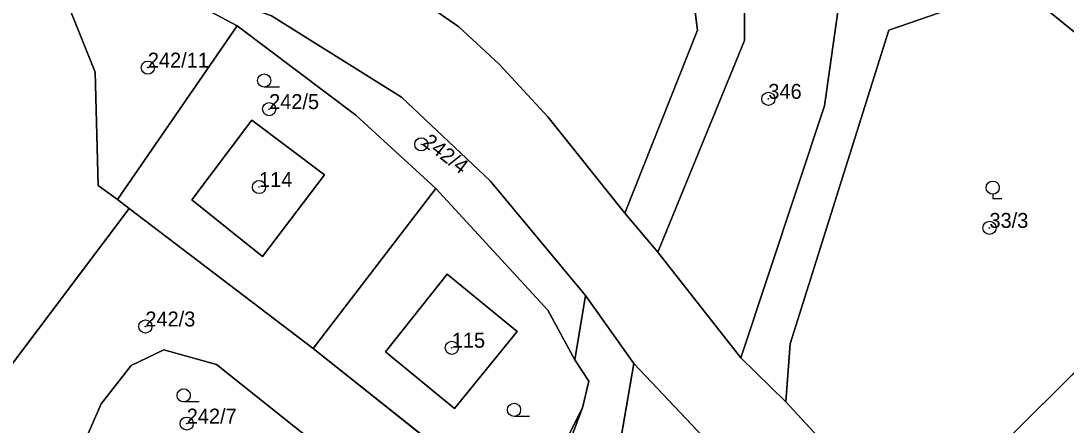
# Model space of a CAD drawing. Extents: x -652854 to -650068, y -1097661 to -1095417.
# Drawn here: x -650938.6 to -650819.6, y -1096045.2 to -1095999.2 of the extents above; entities that cross this region are included whole.
import ezdxf

# ---------------------------------------------------------------- set-up
doc = ezdxf.new("R2010")
doc.units = 0
for name, color, linetype in [('Definiční body parcel', 7, 'Continuous'), ('Hranice parcel', 7, 'Continuous'), ('Obvody jako plochy', 7, 'Continuous'), ('Parcelní čísla', 7, 'Continuous'), ('Značky kultur', 7, 'Continuous')]:
    doc.layers.add(name, color=color, linetype=linetype)

msp = doc.modelspace()

# ---------------------------------------------------------------- linework, layer by layer
at = {"layer": 'Definiční body parcel'}
for centre, radius in [((-650924.13, -1096004.54), 0.75), ((-650924.13, -1096004.54), 0.0327), ((-650853.49, -1096008.09), 0.75), ((-650853.49, -1096008.09), 0.0327), ((-650910.32, -1096009.26), 0.75), ((-650910.32, -1096009.26), 0.0327), ((-650893, -1096013.27), 0.75), ((-650893, -1096013.27), 0.0327), ((-650911.47, -1096018.13), 0.75), ((-650911.47, -1096018.13), 0.0327), ((-650828.32, -1096022.78), 0.75), ((-650828.32, -1096022.78), 0.0327), ((-650924.41, -1096034), 0.75), ((-650924.41, -1096034), 0.0327), ((-650889.53, -1096036.42), 0.75), ((-650889.53, -1096036.42), 0.0327), ((-650919.7, -1096045.05), 0.75), ((-650919.7, -1096045.05), 0.0327)]:
    msp.add_circle(centre, radius, dxfattribs=at)
at = {"layer": 'Hranice parcel'}
for p, q in [((-650861.57, -1096000.28), (-650865.79, -1095966.45)), ((-650856.25, -1095986.12), (-650856.19, -1096001.44)), ((-650888.72, -1095999.9), (-650906.97, -1095987.24)), ((-650913.95, -1095999.79), (-650928.95, -1095991.79)), ((-650847.08, -1096008.9), (-650844.73, -1095992.23)), ((-650934.27, -1095994.75), (-650930.14, -1096005.05)), ((-650839.79, -1096000.27), (-650825.13, -1095995.2)), ((-650825.13, -1095995.2), (-650797.14, -1096017.98)), ((-650895.24, -1096007.92), (-650910.04, -1095998.66)), ((-650927.6, -1096019.54), (-650913.95, -1095999.79)), ((-650913.95, -1095999.79), (-650900.46, -1096009.94)), ((-650884.15, -1096004.16), (-650888.72, -1095999.9)), ((-650869.83, -1096021.1), (-650861.57, -1096000.28)), ((-650851, -1096035.98), (-650839.79, -1096000.27)), ((-650856.19, -1096001.44), (-650866.08, -1096025.56)), ((-650878.58, -1096010.13), (-650884.15, -1096004.16)), ((-650930.14, -1096005.05), (-650929.8, -1096017.97)), ((-650885.14, -1096017.44), (-650895.24, -1096007.92)), ((-650856.61, -1096037.55), (-650847.08, -1096008.9)), ((-650919.13, -1096019.58), (-650912.29, -1096010.52)), ((-650912.29, -1096010.52), (-650904.02, -1096016.76)), ((-650900.46, -1096009.94), (-650891.33, -1096018.28)), ((-650869.83, -1096021.1), (-650878.58, -1096010.13)), ((-650904.02, -1096016.76), (-650911.07, -1096026.02)), ((-650874.29, -1096030.48), (-650885.14, -1096017.44)), ((-650929.8, -1096017.97), (-650927.6, -1096019.54)), ((-650891.33, -1096018.28), (-650905.32, -1096036.52)), ((-650878.59, -1096032.13), (-650891.33, -1096018.28)), ((-650797.14, -1096017.98), (-650837.43, -1096057.82)), ((-650927.6, -1096019.54), (-650926.24, -1096020.58)), ((-650911.07, -1096026.02), (-650919.13, -1096019.58)), ((-650926.24, -1096020.58), (-650947.07, -1096048.17)), ((-650926.24, -1096020.58), (-650905.32, -1096036.52)), ((-650866.08, -1096025.56), (-650869.83, -1096021.1)), ((-650866.08, -1096025.56), (-650856.61, -1096037.55)), ((-650890.06, -1096028.04), (-650897.06, -1096036.9)), ((-650882.07, -1096034.56), (-650890.06, -1096028.04)), ((-650874.29, -1096030.48), (-650875.52, -1096037.79)), ((-650868.81, -1096038.2), (-650874.29, -1096030.48)), ((-650875.52, -1096037.79), (-650878.59, -1096032.13)), ((-650889.23, -1096043.33), (-650882.07, -1096034.56)), ((-650922.29, -1096036.66), (-650926.04, -1096038.44)), ((-650916.32, -1096038.32), (-650922.29, -1096036.66)), ((-650905.32, -1096036.52), (-650886.47, -1096051.45)), ((-650851.49, -1096042.56), (-650851, -1096035.98)), ((-650897.06, -1096036.9), (-650889.23, -1096043.33)), ((-650873.91, -1096040.24), (-650875.52, -1096037.79)), ((-650856.61, -1096037.55), (-650851.49, -1096042.56)), ((-650926.04, -1096038.44), (-650929.43, -1096042.79)), ((-650904.71, -1096047.58), (-650916.32, -1096038.32)), ((-650868.81, -1096038.2), (-650871.08, -1096051.36)), ((-650844.12, -1096064.27), (-650868.81, -1096038.2)), ((-650874.66, -1096043.25), (-650873.91, -1096040.24)), ((-650929.43, -1096042.79), (-650935.88, -1096057.57)), ((-650837.43, -1096057.82), (-650851.49, -1096042.56)), ((-650874.66, -1096043.25), (-650884.57, -1096069.52)), ((-650875.54, -1096045.04), (-650874.66, -1096043.25)), ((-650878.99, -1096052.02), (-650875.54, -1096045.04))]:
    msp.add_line(p, q, dxfattribs=at)
at = {"layer": 'Obvody jako plochy'}
for points in [[(-650815.91, -1096079.94), (-650837.43, -1096057.82), (-650851.49, -1096042.56), (-650856.61, -1096037.55), (-650866.08, -1096025.56), (-650869.83, -1096021.1), (-650878.58, -1096010.13), (-650884.15, -1096004.16), (-650888.72, -1095999.9), (-650906.97, -1095987.24), (-650919.07, -1095983.1), (-650939.79, -1095976.94), (-650942.73, -1095975.31), (-650965.11, -1095955.28), (-650999.89, -1095931.88), (-651069.69, -1095883.2), (-651088.16, -1095874.33), (-651093.24, -1095871.75), (-651106.05, -1095871.75), (-651124.53, -1095872.94)], [(-651111.53, -1095882.37), (-651098.01, -1095884.51), (-651076.72, -1095891.08), (-651069.09, -1095896.55), (-651006, -1095940.92), (-650970.52, -1095965.45), (-650947.06, -1095985.27), (-650941.58, -1095987.24), (-650928.95, -1095991.79), (-650910.04, -1095998.66), (-650895.24, -1096007.92), (-650885.14, -1096017.44), (-650874.29, -1096030.48), (-650868.81, -1096038.2), (-650844.12, -1096064.27), (-650836.01, -1096073.17), (-650788.5, -1096124.42)], [(-650904.08, -1096145.3), (-650901.13, -1096135.45), (-650897.38, -1096119.26), (-650893.01, -1096103.89), (-650871.08, -1096051.36), (-650868.81, -1096038.2), (-650874.29, -1096030.48), (-650875.52, -1096037.79), (-650873.91, -1096040.24), (-650874.66, -1096043.25), (-650884.57, -1096069.52), (-650902.03, -1096119.57), (-650909.81, -1096151.69)]]:
    msp.add_lwpolyline(points, dxfattribs=at)
for points in [[(-650861.2, -1095966.88), (-650864, -1095957.32), (-650870.42, -1095945.56), (-650883.1, -1095928.38), (-650889.88, -1095920.1), (-650889.39, -1095918.87), (-650896.67, -1095915.35), (-650898.83, -1095918.21), (-650888.97, -1095929.69), (-650880.92, -1095939.45), (-650877.8, -1095945.22), (-650865.79, -1095966.45), (-650861.57, -1096000.28), (-650869.83, -1096021.1), (-650866.08, -1096025.56), (-650856.19, -1096001.44), (-650856.25, -1095986.12)], [(-650869.83, -1096021.1), (-650861.57, -1096000.28), (-650865.79, -1095966.45), (-650877.8, -1095945.22), (-650906.97, -1095987.24), (-650888.72, -1095999.9), (-650884.15, -1096004.16), (-650878.58, -1096010.13)], [(-650844.61, -1095959.76), (-650854.5, -1095965.91), (-650851.37, -1095965.97), (-650850.67, -1095975.72), (-650844.49, -1095970.31), (-650829.16, -1095986.05), (-650835.66, -1095991.9), (-650844.73, -1095992.23), (-650847.08, -1096008.9), (-650856.61, -1096037.55), (-650851.49, -1096042.56), (-650851, -1096035.98), (-650839.79, -1096000.27), (-650825.13, -1095995.2), (-650797.14, -1096017.98), (-650789.35, -1096010.06), (-650786.65, -1096007.6), (-650818.08, -1095980.3), (-650830.01, -1095970.16)], [(-650854.5, -1095965.91), (-650861.2, -1095966.88), (-650856.25, -1095986.12), (-650856.19, -1096001.44), (-650866.08, -1096025.56), (-650856.61, -1096037.55), (-650847.08, -1096008.9), (-650844.73, -1095992.23), (-650850.67, -1095975.72), (-650851.37, -1095965.97)], [(-650928.95, -1095991.79), (-650941.58, -1095987.24), (-650943.99, -1095992.27), (-650946.25, -1095992.54), (-650959.24, -1096011.23), (-650948.93, -1096017.64), (-650954.29, -1096026.46), (-650958.9, -1096023.69), (-650976.4, -1096052.35), (-650923.91, -1096091.54), (-650915.34, -1096072.03), (-650914.12, -1096069.22), (-650936.73, -1096059.52), (-650935.88, -1096057.57), (-650947.07, -1096048.17), (-650926.24, -1096020.58), (-650927.6, -1096019.54), (-650929.8, -1096017.97), (-650930.14, -1096005.05), (-650934.27, -1095994.75), (-650932.24, -1095992.24)], [(-650928.95, -1095991.79), (-650932.24, -1095992.24), (-650934.27, -1095994.75), (-650930.14, -1096005.05), (-650929.8, -1096017.97), (-650927.6, -1096019.54), (-650913.95, -1095999.79)], [(-650913.95, -1095999.79), (-650900.46, -1096009.94), (-650891.33, -1096018.28), (-650878.59, -1096032.13), (-650875.52, -1096037.79), (-650874.29, -1096030.48), (-650885.14, -1096017.44), (-650895.24, -1096007.92), (-650910.04, -1095998.66), (-650928.95, -1095991.79)], [(-650851.49, -1096042.56), (-650837.43, -1096057.82), (-650797.14, -1096017.98), (-650825.13, -1095995.2), (-650839.79, -1096000.27), (-650851, -1096035.98)], [(-650927.6, -1096019.54), (-650926.24, -1096020.58), (-650905.32, -1096036.52), (-650891.33, -1096018.28), (-650900.46, -1096009.94), (-650913.95, -1095999.79)], [(-650912.29, -1096010.52), (-650919.13, -1096019.58), (-650911.07, -1096026.02), (-650904.02, -1096016.76)], [(-650912.29, -1096010.52), (-650904.02, -1096016.76), (-650911.07, -1096026.02), (-650919.13, -1096019.58)], [(-650797.14, -1096017.98), (-650837.43, -1096057.82), (-650815.91, -1096079.94), (-650814.51, -1096078.48), (-650793.24, -1096056.1), (-650772.49, -1096033.67), (-650789.35, -1096010.06)], [(-650891.33, -1096018.28), (-650905.32, -1096036.52), (-650886.47, -1096051.45), (-650882.38, -1096052.68), (-650878.99, -1096052.02), (-650875.54, -1096045.04), (-650874.66, -1096043.25), (-650873.91, -1096040.24), (-650875.52, -1096037.79), (-650878.59, -1096032.13)], [(-650926.24, -1096020.58), (-650947.07, -1096048.17), (-650935.88, -1096057.57), (-650929.43, -1096042.79), (-650926.04, -1096038.44), (-650922.29, -1096036.66), (-650916.32, -1096038.32), (-650904.71, -1096047.58), (-650888.23, -1096060.47), (-650885.56, -1096063.83), (-650884.57, -1096069.52), (-650874.66, -1096043.25), (-650875.54, -1096045.04), (-650878.99, -1096052.02), (-650882.38, -1096052.68), (-650886.47, -1096051.45), (-650905.32, -1096036.52)], [(-650890.06, -1096028.04), (-650897.06, -1096036.9), (-650889.23, -1096043.33), (-650882.07, -1096034.56)], [(-650890.06, -1096028.04), (-650882.07, -1096034.56), (-650889.23, -1096043.33), (-650897.06, -1096036.9)], [(-650935.88, -1096057.57), (-650936.73, -1096059.52), (-650914.12, -1096069.22), (-650904.71, -1096047.58), (-650916.32, -1096038.32), (-650922.29, -1096036.66), (-650926.04, -1096038.44), (-650929.43, -1096042.79)], [(-650873.42, -1096064.2), (-650866.17, -1096048.58), (-650844.95, -1096065.9), (-650844.12, -1096064.27), (-650868.81, -1096038.2), (-650871.08, -1096051.36), (-650893.01, -1096103.89), (-650897.38, -1096119.26), (-650894.61, -1096121.58), (-650890.21, -1096108.61), (-650877.58, -1096079.03), (-650880.16, -1096077.08)]]:
    msp.add_lwpolyline(points, close=True, dxfattribs=at)
at = {"layer": 'Značky kultur'}
for p, q in [((-650909.14, -1096006.75), (-650910.89, -1096006.75)), ((-650827.95, -1096018.95), (-650827.95, -1096019.45)), ((-650827.95, -1096019.45), (-650826.927, -1096019.45)), ((-650918.3, -1096042.59), (-650920.05, -1096042.59)), ((-650880.69, -1096044.24), (-650882.44, -1096044.24))]:
    msp.add_line(p, q, dxfattribs=at)
for centre in [(-650910.89, -1096006), (-650827.95, -1096018.2), (-650920.05, -1096041.84), (-650882.44, -1096043.49)]:
    msp.add_circle(centre, 0.75, dxfattribs=at)

# ---------------------------------------------------------------- texts
at = {"layer": 'Parcelní čísla'}
for s, p in [('242/11', (-650924.13, -1096004.54)), ('346', (-650853.49, -1096008.09)), ('242/5', (-650910.32, -1096009.26)), ('114', (-650911.47, -1096018.13)), ('33/3', (-650828.32, -1096022.78)), ('242/3', (-650924.41, -1096034)), ('115', (-650889.53, -1096036.42)), ('242/7', (-650919.7, -1096045.05))]:
    msp.add_text(s, height=1.7, dxfattribs=at).set_placement(p)
msp.add_text('242/4', height=1.7, rotation=322.434, dxfattribs=at).set_placement((-650893, -1096013.27))

doc.saveas('drawing.dxf')
